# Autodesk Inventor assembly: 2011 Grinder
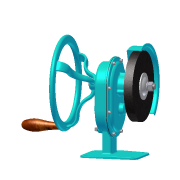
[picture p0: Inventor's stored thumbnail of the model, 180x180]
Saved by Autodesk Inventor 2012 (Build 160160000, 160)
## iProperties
Created: 2010-12
Part Number: 2011 Grinder
Document SubType Name: Assembly
Designer: Thom Tremblay
Author: Thom Tremblay
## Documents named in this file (28)
- C:\Users\VMuser\Desktop\Inventor 2012 Essentials\Assemblies\Chapter 6\c6-01.iam
- C:\Users\VMuser\Desktop\Inventor 2012 Essentials\Parts\Chapter 6\c6-01.ipt
- C:\Users\VMuser\Desktop\Inventor 2012 Essentials\Parts\Chapter 6\c6-02.ipt
- C:\Users\VMuser\Desktop\Inventor 2012 Essentials\Assemblies\Chapter 6\c6-01\Design Accelerator\Spur Gears1.iam
- C:\Users\VMuser\Desktop\Inventor 2012 Essentials\Assemblies\Chapter 6\c6-01\Design Accelerator\Spur Gears2.iam
- C:\Users\VMuser\Desktop\Inventor 2012 Essentials\Parts\Chapter 6\c6-03.ipt
- C:\Users\VMuser\Desktop\Inventor 2012 Essentials\Parts\Chapter 6\c6-04.ipt
- C:\Users\VMuser\Desktop\Inventor 2012 Essentials\Parts\Chapter 6\c6-05.ipt
- C:\Users\VMuser\Desktop\Inventor 2012 Essentials\Parts\Chapter 6\c6-08.ipt
- C:\Users\VMuser\Desktop\Inventor 2012 Essentials\Parts\Chapter 6\c6-06.ipt
- C:\Users\VMuser\Desktop\Inventor 2012 Essentials\Parts\Chapter 6\c6-07.ipt
- C:\Users\VMuser\Desktop\Inventor 2012 Essentials\Content Center Files\en-US\ANSI B93.98M\ANSI_B93.98M - 15x35x7-Type 2.ipt
- C:\Users\VMuser\Desktop\Inventor 2012 Essentials\Content Center Files\en-US\SKF B - angular contact\SKF B7202 BE.ipt
- C:\Users\VMuser\Desktop\Inventor 2012 Essentials\Content Center Files\en-US\IS 7483\IS 7483 - M4 x 8.ipt
- C:\Users\VMuser\Desktop\Inventor 2012 Essentials\Assemblies\Chapter 6\c6-01\Design Accelerator\Bolted Connection3.iam
- C:\Users\VMuser\Desktop\Inventor 2012 Essentials\Content Center Files\en-US\ISO 2795  F\ISO 2795 - 10 x 14 x 10F.ipt
- C:\Users\VMuser\Desktop\Inventor 2012 Essentials\Assemblies\Chapter 6\c6-01\Design Accelerator\Shaft4.iam
- C:\Users\VMuser\Desktop\Inventor 2012 Essentials\Assemblies\Chapter 6\c6-01\Design Accelerator\Shaft6.iam
- C:\Users\VMuser\Desktop\Inventor 2012 Essentials\Assemblies\Chapter 6\c6-01\Design Accelerator\Spur Gears4.iam
- C:\Users\VMuser\Desktop\Inventor 2012 Essentials\Assemblies\Chapter 6\c6-01\Design Accelerator\Shaft5.iam
- C:\Users\VMuser\Desktop\Inventor 2012 Essentials\Content Center Files\en-US\STN 022930\STN 022930 - 10.ipt
- C:\Users\VMuser\Desktop\Inventor 2012 Essentials\Content Center Files\en-US\STN 022930\STN 022930 - 15.ipt
- C:\Users\VMuser\Desktop\Inventor 2012 Essentials\Assemblies\Chapter 6\c6-01\Design Accelerator\Spur Gears5.iam
- C:\Users\VMuser\Desktop\Inventor 2012 Essentials\Content Center Files\en-US\DIN 128\DIN 128 - A12.ipt
- C:\Users\VMuser\Desktop\Inventor 2012 Essentials\Assemblies\Chapter 6\c6-01\Design Accelerator\Bolted Connection4.iam
- C:\Users\VMuser\Desktop\Inventor 2012 Essentials\Content Center Files\en-US\ISO 4032\ISO 4032 - M12ISO.ipt
- C:\Users\VMuser\Desktop\Inventor 2012 Essentials\Content Center Files\en-US\ISO 4145 T8\ISO 4145 Plug T8 1_8.ipt
- C:\Users\VMuser\Desktop\Inventor 2012 Essentials\Assemblies\Chapter 6\c6-01\Design Accelerator\Key Connection1.iam
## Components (32 placed, 21 different names)
1. c6-01:1 — Insert:1, Angle:1, Flush:3, Insert:27, Insert:28, Insert:39
2. c6-02:1 — Insert:1, Angle:1, Insert:17, Insert:18, Insert:25, Insert:26, Mate:3, Mate:7, Mate:8, Insert:40
3. ANSI/B93.98M 15x35x7-Type 2:1 — Insert:40
4. Spur Gears:1 [sub-assembly]
5. Spur Gears:2 [sub-assembly] — Rotation:3, Rotation:2, Mate:4, Flush:4, Angle:15
6. c6-03:1 — Flush:3
7. c6-04:1 — Insert:10, Insert:35, Angle:9, Mate:5, Angle:13
8. c6-05:1 — Insert:10
9. c6-08:1 — Insert:13, Insert:16, Insert:36
10. c6-08:2 — Insert:13
11. c6-06:1 — Insert:16, Angle:11, Angle:12
12. c6-07:1 — Insert:17, Insert:18
13. SKF B- Angular contact SKF B7202 BE:1 — Insert:25
14. IS 7483 M4 x 8:1
15. IS 7483 M4 x 8:2
16. Bolted Connection:2 [sub-assembly] — Mate:7, Mate:8
17. ISO 2795 (Flanged) 10 x 14 x 10:1 — Insert:26
18. ISO 2795 (Flanged) 10 x 14 x 10:2 — Insert:27, Insert:30
19. ISO 2795 (Flanged) 10 x 14 x 10:3 — Insert:28, Insert:34
20. Shaft:1 [sub-assembly] — Rotation:1, Insert:34, Insert:35, Angle:9, Mate:6
21. Shaft:2 [sub-assembly] — Insert:30, Rotation:1, Flush:3, Rotation:3, Mate:4, Flush:4, Flush:5, Angle:14, Mate:9, Angle:15
22. Spur Gears:3 [sub-assembly]
23. Shaft:3 [sub-assembly] — Flush:3, Mate:3, Rotation:2, Insert:36, Angle:12
24. STN 022930 10:1
25. STN 022930 15:1
26. STN 022930 15:2
27. Spur Gears:4 [sub-assembly]
28. DIN 128 A12:1 — Angle:10
29. Bolted Connection:3 [sub-assembly] — Mate:5, Mate:6
30. ISO 4032 M12:1 — Angle:10, Angle:11
31. ISO 4145 Plug T8 1/8:1 — Insert:39
32. Key Connection:1 [sub-assembly] — Flush:5, Angle:14, Mate:9
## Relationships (38: Insert 16, Angle 8, Mate 7, Flush 4, RelateRotation 3)
- Insert:1: c6-01:1 ↔ c6-02:1
- Angle:1: c6-01:1 ↔ c6-02:1
- Flush:3: c6-01:1 ↔ c6-03:1
- Insert:10: c6-04:1 ↔ c6-05:1
- Insert:13: c6-08:1 ↔ c6-08:2
- Insert:16: c6-08:1 ↔ c6-06:1
- Insert:17: c6-02:1 ↔ c6-07:1
- Insert:18: c6-02:1 ↔ c6-07:1
- Insert:25: c6-02:1 ↔ SKF B- Angular contact SKF B7202 BE:1
- Insert:26: c6-02:1 ↔ ISO 2795 (Flanged) 10 x 14 x 10:1
- Insert:27: c6-01:1 ↔ ISO 2795 (Flanged) 10 x 14 x 10:2
- Insert:28: c6-01:1 ↔ ISO 2795 (Flanged) 10 x 14 x 10:3
- Insert:30: ISO 2795 (Flanged) 10 x 14 x 10:2 ↔ Shaft:2
- Rotation:1 [RelateRotation]: Shaft:1 ↔ Shaft:2
- Flush:3: Shaft:2 ↔ Shaft:3
- Mate:3: c6-02:1 ↔ Shaft:3
- Insert:34: ISO 2795 (Flanged) 10 x 14 x 10:3 ↔ Shaft:1
- Insert:35: c6-04:1 ↔ Shaft:1
- Angle:9: c6-04:1 ↔ Shaft:1
- Rotation:2 [RelateRotation]: Spur Gears:2 ↔ Shaft:3
- Rotation:3 [RelateRotation]: Spur Gears:2 ↔ Shaft:2
- Mate:4: Spur Gears:2 ↔ Shaft:2
- Flush:4: Spur Gears:2 ↔ Shaft:2
- Insert:36: c6-08:1 ↔ Shaft:3
- Mate:5: c6-04:1 ↔ Bolted Connection:3
- Mate:6: Shaft:1 ↔ Bolted Connection:3
- Angle:10: DIN 128 A12:1 ↔ ISO 4032 M12:1
- Angle:11: c6-06:1 ↔ ISO 4032 M12:1
- Angle:12: c6-06:1 ↔ Shaft:3
- Insert:39: c6-01:1 ↔ ISO 4145 Plug T8 1/8:1
- Angle:13: c6-04:1
- Mate:7: c6-02:1 ↔ Bolted Connection:2
- Mate:8: c6-02:1 ↔ Bolted Connection:2
- Flush:5: Shaft:2 ↔ Key Connection:1
- Angle:14: Shaft:2 ↔ Key Connection:1
- Mate:9: Shaft:2 ↔ Key Connection:1
- Angle:15: Spur Gears:2 ↔ Shaft:2
- Insert:40: c6-02:1 ↔ ANSI/B93.98M 15x35x7-Type 2:1
